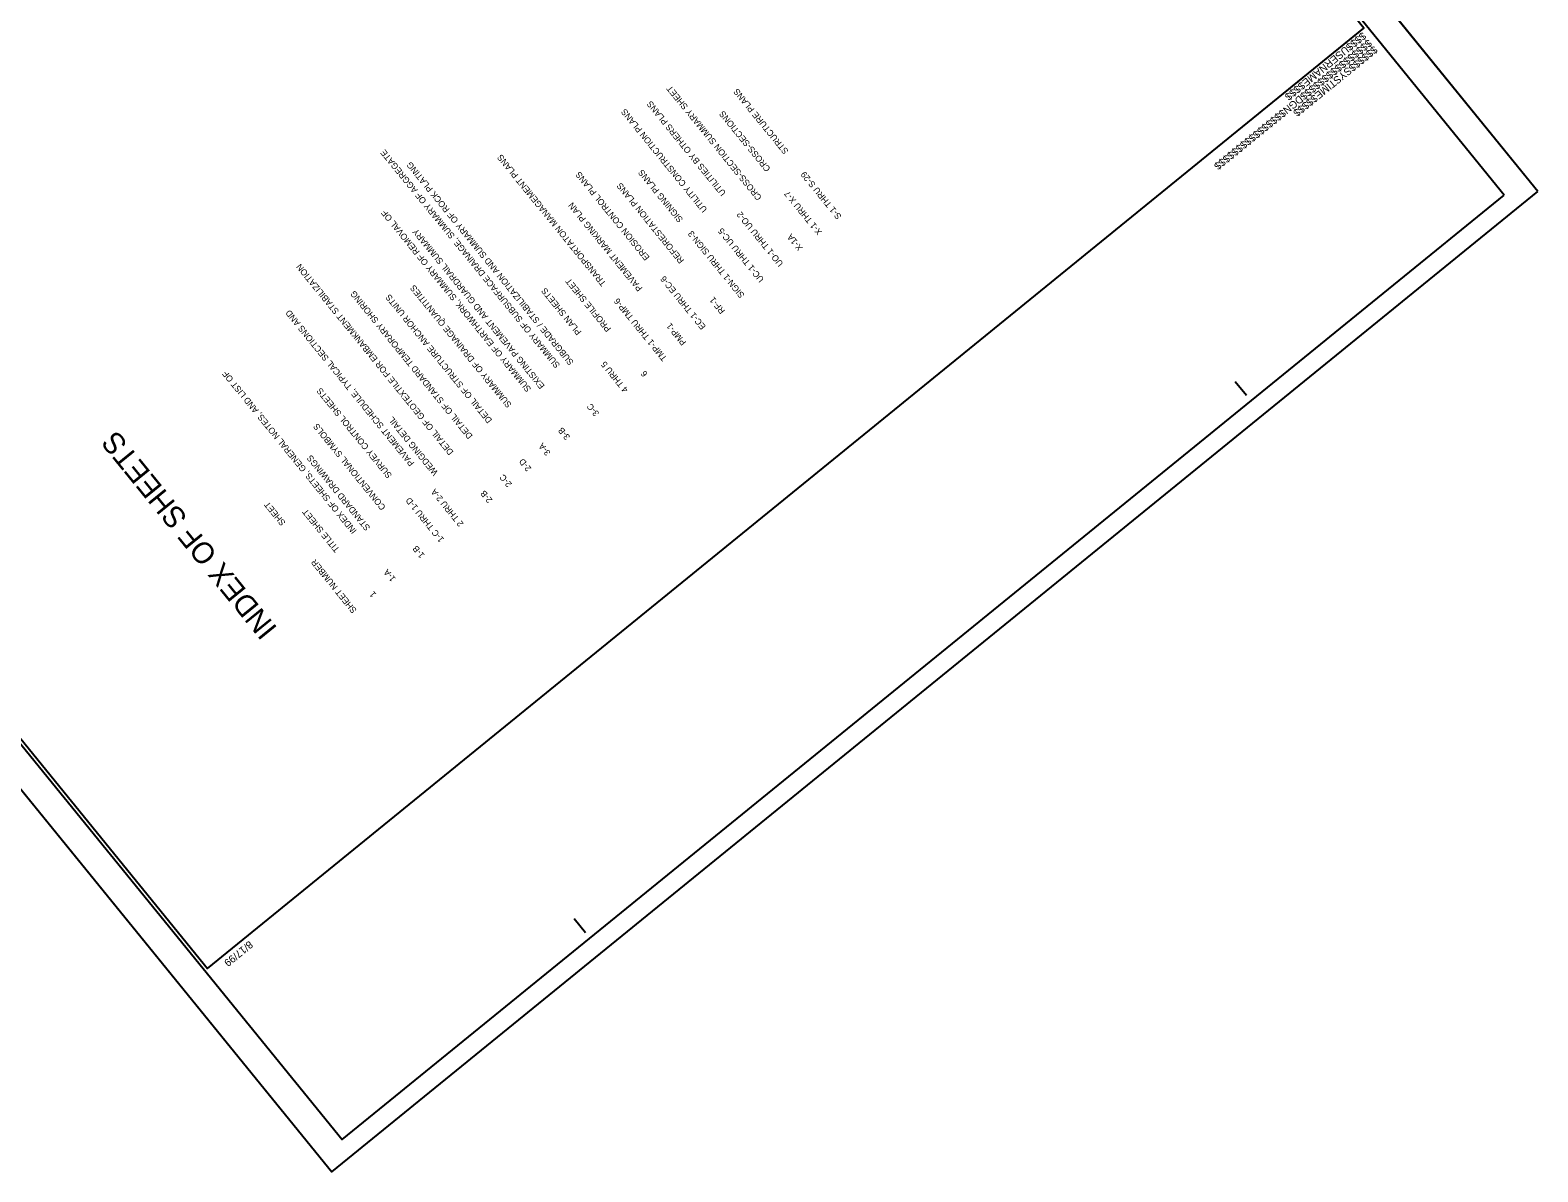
# Model space of a CAD drawing. Extents: x 2596486 to 2602076, y 851390 to 856110.
# Drawn here: x 2601014 to 2602076, y 852392 to 853196 of the extents above; entities that cross this region are included whole.
import ezdxf

# ---------------------------------------------------------------- set-up
doc = ezdxf.new("R2010")
doc.units = 0
for name, color, linetype in [('Sheet Cutting Line CELL', 7, 'Continuous'), ('Sheet Data Text CELL', 7, 'Continuous'), ('Sheet Plan CELL', 7, 'Continuous'), ('Sheet Plot Border Inside CELL', 7, 'Continuous'), ('Sheet Plot Border Outside CELL', 7, 'Continuous')]:
    doc.layers.add(name, color=color, linetype=linetype)

msp = doc.modelspace()

# ---------------------------------------------------------------- linework, layer by layer
at = {"layer": 'Sheet Cutting Line CELL'}
for p, q in [((2602075.7, 853082.8), (2601013.9, 854389.2)), ((2600164.2, 853698.5), (2601226, 852392.1)), ((2601226, 852392.1), (2602075.7, 853082.8))]:
    msp.add_line(p, q, dxfattribs=at)
at = {"layer": 'Sheet Plan CELL'}
for p, q in [((2601870.4, 852939), (2601862.5, 852948.7)), ((2601404.8, 852560.6), (2601396.9, 852570.3)), ((2601138.4, 852535.5), (2601138.4, 852535.5))]:
    msp.add_line(p, q, dxfattribs=at)
msp.add_lwpolyline([(2600192.4, 853699.5), (2601138.4, 852535.5), (2601953.2, 853197.8), (2601007.2, 854361.8)], close=True, dxfattribs=at)
at = {"layer": 'Sheet Plot Border Inside CELL'}
msp.add_lwpolyline([(2602052, 853080.2), (2601001.2, 854373.1), (2600182.5, 853707.7), (2601233.3, 852414.8)], close=True, dxfattribs=at)
at = {"layer": 'Sheet Plot Border Outside CELL'}
msp.add_lwpolyline([(2602075.7, 853082.8), (2601013.9, 854389.2), (2600164.2, 853698.5), (2601226, 852392.1)], close=True, dxfattribs=at)

# ---------------------------------------------------------------- texts
at = {"layer": 'Sheet Data Text CELL'}
for s, height, rotation, p in [('X-1A                    CROSS-SECTION SUMMARY SHEET', 4.4, 129.1028, (2601558.1, 853043.2)), ('S-1 THRU S-29           STRUCTURE PLANS', 4.4, 129.1028, (2601585.4, 853065.4)), ('UO-1 THRU UO-2          UTILITIES BY OTHERS PLANS', 4.4, 129.1028, (2601544.4, 853032.1)), ('UC-1 THRU UC-5          UTILITY CONSTRUCTION PLANS', 4.4, 129.1028, (2601530.8, 853021)), ('X-1 THRU X-7            CROSS-SECTIONS', 4.4, 129.1028, (2601571.7, 853054.3)), ('3-C                     SUMMARY OF SUBSURFACE DRAINAGE, SUMMARY OF AGGREGATE', 4.4, 129.1028, (2601414.7, 852926.6)), ('                        SUBGRADE / STABILIZATION AND SUMMARY OF ROCK PLATING', 4.4, 129.1028, (2601421.5, 852932.2)), ('TMP-1 THRU TMP-6        TRANSPORTATON MANAGEMENT PLANS', 4.4, 129.1028, (2601462.5, 852965.5)), ('EC-1 THRU EC-6          EROSION CONTROL PLANS', 4.4, 129.1028, (2601489.8, 852987.7)), ('RF-1                    REFORESTATION PLANS', 4.4, 129.1028, (2601503.4, 852998.8)), ('SIGN-1 THRU SIGN-3      SIGNING PLANS', 4.4, 129.1028, (2601517.1, 853009.9)), ('3-B                     SUMMARY OF EARTHWORK, SUMMARY OF REMOVAL OF  ', 4.4, 129.1028, (2601394.2, 852910)), ('PMP-1                   PAVEMENT MARKING PLAN', 4.4, 129.1028, (2601476.1, 852976.6)), ('                        EXISTING PAVEMENT AND GUARDRAIL SUMMARY', 4.4, 129.1028, (2601401, 852915.5)), ('2-B                     DETAIL OF GEOTEXTILE FOR EMBANKMENT STABILIZATION', 4.4, 129.1028, (2601339.5, 852865.6)), ('3-A                     SUMMARY OF DRAINAGE QUANTITIES', 4.4, 129.1028, (2601380.5, 852898.9)), ('4 THRU 5                PLAN SHEETS', 4.4, 129.1028, (2601435.2, 852943.3)), ('6                       PROFILE SHEET  ', 4.4, 129.1028, (2601448.8, 852954.4)), ('2-C                     DETAIL OF STANDARD TEMPORARY SHORING', 4.4, 129.1028, (2601353.2, 852876.7)), ('2-D                     DETAIL OF STRUCTURE ANCHOR UNITS', 4.4, 129.1028, (2601366.9, 852887.8)), ('2 THRU 2-A              PAVEMENT SCHEDULE, TYPICAL SECTIONS AND ', 4.4, 129.1028, (2601319.1, 852848.9)), ('1-A                     INDEX OF SHEETS, GENERAL NOTES, AND LIST OF ', 4.4, 129.1028, (2601271.3, 852810.1)), ('1-C THRU 1-D            SURVEY CONTROL SHEETS', 4.4, 129.1028, (2601305.4, 852837.8)), ('1-B                     CONVENTIONAL SYMBOLS ', 4.4, 129.1028, (2601291.7, 852826.7)), ('                        WEDGING DETAIL ', 4.4, 129.1028, (2601325.9, 852854.5)), ('INDEX OF SHEETS ', 15, 129.1027, (2601188.2, 852775.1)), ('                        STANDARD DRAWINGS', 4.4, 129.1028, (2601278.1, 852815.6)), ('SHEET NUMBER                    SHEET   ', 4.4, 129.1028, (2601243.9, 852787.9)), ('1                       TITLE SHEET', 4.4, 129.1028, (2601257.6, 852799))]:
    msp.add_text(s, height=height, rotation=rotation, dxfattribs=at).set_placement(p)
at = {"layer": 'Sheet Plan CELL'}
for s, p in [('$$$$USERNAME$$$$', (2601952.1, 853195.4)), ('$$$$$$$$$$$$$$$$DGN$$$$$$$$$$$$$$$$', (2601956.2, 853190.3)), ('$$$$$$SYSTIME$$$$$', (2601960.1, 853185.7)), ('8/17/99', (2601167.8, 852555.2))]:
    msp.add_text(s, height=5.25, rotation=219.1028, dxfattribs=at).set_placement(p)

doc.saveas('drawing.dxf')
